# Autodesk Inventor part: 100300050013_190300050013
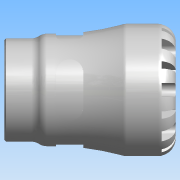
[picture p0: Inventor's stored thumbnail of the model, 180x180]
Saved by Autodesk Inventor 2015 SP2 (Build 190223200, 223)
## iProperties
Created: 2016-12
Part Number: 100300050013_190300050013
Material: PVC-Piping
Description: PLASSON FEMALE ADAPTOR 50X1.1/4" SERIES 1
Document SubType Name: Modeling
Designer: KIM
Mass: 664.223 g
Surface Area: 733.008 cm^2
Volume: 474.445 cm^3
Density: 1.4 g/cm^3
Appearance: Smooth - White
Author: KIM
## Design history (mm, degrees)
derived "1003.ipt"
feature "Solid1::1003.ipt"
tag "TaggingFeature1"
body "Solid1"
other parameters: "d1" = 32.76, "d3" = 62.5, "d4" = 85, "d6" = 78, "d8" = 72.25, "d13" = 9, "d14" = 9, "d15" = 0, "d17" = 360 deg, "d19" = 8 deg, "d20" = 1, "d21" = 1, "d22" = 8 deg, "d24" = 0, "d26" = 360 deg, "d32" = 8.5, "d33" = 8.5, "d39" = 1.16856, "d42" = 38.952, "d43" = 66.3, "d46" = 4.16667, "d47" = 24, "d48" = 37.0044, "d50" = 2.64, "d51" = 0.85, "d54" = 17.5, "d55" = 11, "d57" = 17.64, "d58" = 0, "d68" = 360 deg, "d72" = 1, "d74" = 0, "d76" = 14.875, "E_" = 85, "l_" = 78, "Rp" = 38.952, "l_2" = 24, "d9" = 11.25, "d11" = 85, "d12" = 62.5, "d49" = 8
